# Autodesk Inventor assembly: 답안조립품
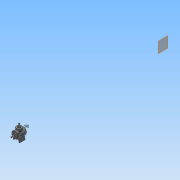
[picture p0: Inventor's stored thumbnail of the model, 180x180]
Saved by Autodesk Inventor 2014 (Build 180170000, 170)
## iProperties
Created: 2015-01
Part Number: 답안조립품
Document SubType Name: Assembly
Designer: net
Author: net
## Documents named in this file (15)
- C:\Users\net\Desktop\450105V1039\답안조립품.iam
- C:\Users\net\Desktop\450105V1039\본체.ipt
- C:\Users\net\Desktop\450105V1039\커버.ipt
- C:\Users\net\Desktop\450105V1039\베어링 6203.ipt
- C:\Users\net\Desktop\450105V1039\서브 축.ipt
- 서브 축.ipt
- C:\Users\net\Desktop\450105V1039\커버2.ipt
- C:\Users\net\Desktop\450105V1039\메인 축.ipt
- 메인 축.ipt
- C:\Users\net\Desktop\450105V1039\키 4x4.ipt
- C:\Users\net\Desktop\450105V1039\서브 베벨기어.ipt
- C:\Users\net\Desktop\450105V1039\메인 베벨기어.ipt
- C:\Users\net\Desktop\450105V1039\키 5x5.ipt
- C:\Users\net\Desktop\450105V1039\오일실.ipt
- C:\Users\net\Desktop\450105V1039\M4.ipt
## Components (12 placed, 1 different names)
1. M4:6
2. M4:7
3. M4:8
4. M4:9
5. M4:5
6. M4:10
7. M4:11
8. M4:12
9. M4:13
10. M4:14
11. M4:15
12. M4:16
